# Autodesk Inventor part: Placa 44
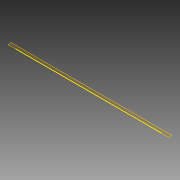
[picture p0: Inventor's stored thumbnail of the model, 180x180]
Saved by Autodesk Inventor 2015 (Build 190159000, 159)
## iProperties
Created: 2015-04
Part Number: Placa 44
Material: Generic
Document SubType Name: Modeling
Designer: suporte
Density: 1 g/cm^3
Appearance: Default
Author: suporte
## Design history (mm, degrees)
workplane "Work Plane1"
sketch "Sketch1"
  geometry: L1 (0, 0)-(615, 0) reference; L2 (0, 12.5)-(615, 12.5) reference; L3 (615, 12.5)-(0, 12.5); L4 (0, 12.5)-(0, -87.5); L5 (0, -87.5)-(615, -87.5); L6 (615, -87.5)-(615, 12.5); L7 (715, -87.5)-(-985, -87.5) reference; 1 further point
  constraints: 8 end point, 2 parallel, 2 point on line, 1 horizontal, 1 midpoint, 1 perpendicular
extrude "Extrusion1" new body sketch "Sketch1" distance "d0" = 12.5; taper "d1" = 0 deg
body "Solid1"
node "Reference1"
node "Reference2"
node "Reference3"
